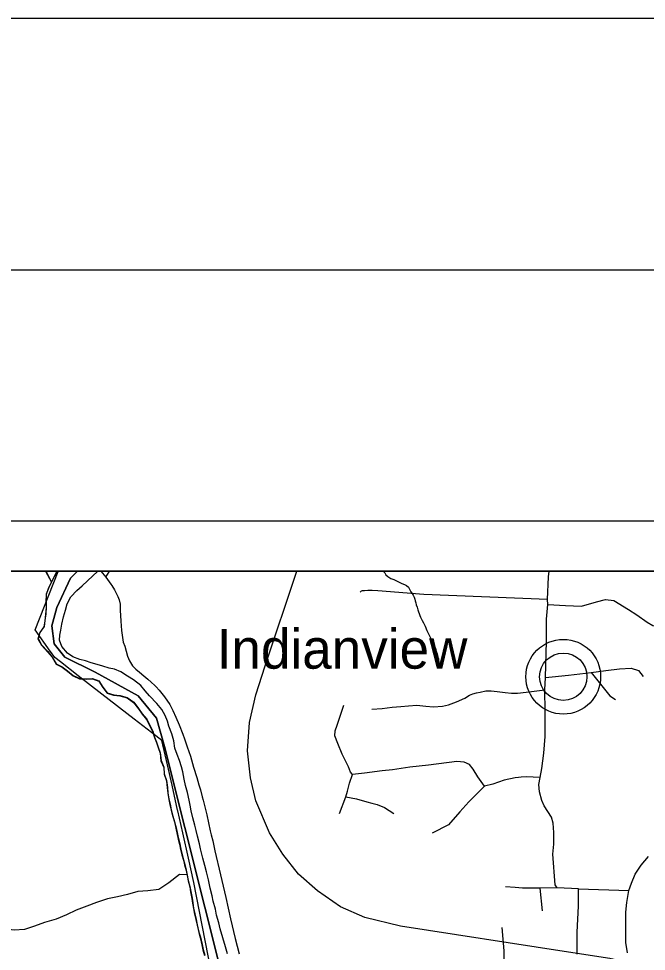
# Model space of a CAD drawing. Extents: x 44.2 to 78.2, y 4.5 to 26.5.
# Drawn here: x 47.924 to 49.173, y 24.644 to 26.501 of the extents above; entities that cross this region are included whole.
import ezdxf

# ---------------------------------------------------------------- set-up
doc = ezdxf.new("R2010")
doc.units = 0
for name, color, linetype in [('GM_X_County_Road', 7, 'Continuous'), ('GM_X_Interstate_Route', 7, 'Continuous'), ('GM_X_Major_River', 7, 'Continuous'), ('GM_X_Minor_River', 7, 'Continuous'), ('GM_X_Rail_Line', 7, 'Continuous'), ('GM_X_State_Route', 7, 'Continuous'), ('GM_X_Township_Road', 7, 'Continuous'), ('GM_X_Unincorporated', 7, 'Continuous'), ('GM_X_Unincorporated_Location', 7, 'Continuous'), ('GM_X_Unincorporated_Text', 7, 'Continuous'), ('SH_Border', 7, 'Continuous'), ('SH_Cut_Line', 7, 'Continuous'), ('SH_Data', 7, 'Continuous')]:
    doc.layers.add(name, color=color, linetype=linetype)

msp = doc.modelspace()

# ---------------------------------------------------------------- linework, layer by layer
at = {"layer": 'GM_X_County_Road'}
for points in [[(49.0354, 24.6387), (49.0354, 24.6825), (49.0377, 24.7339), (49.0377, 24.7688), (48.9957, 24.7705), (48.9915, 24.7764), (48.9868, 24.8374), (48.9889, 24.8572), (48.9889, 24.8804), (48.9878, 24.8992), (48.9844, 24.9111), (48.97, 24.9339), (48.9652, 24.9443), (48.9601, 24.962), (48.9593, 24.976), (48.9615, 24.9904), (48.9652, 25.0085), (48.9689, 25.0387), (48.9715, 25.0716), (48.9715, 25.1225), (48.9708, 25.1646), (48.9722, 25.1893), (48.9741, 25.2616), (48.9746, 25.3056), (48.9772, 25.3347), (48.9765, 25.345), (48.9783, 25.3901), (48.9795, 25.4014)], [(49.1352, 24.6408), (49.132, 24.6614), (49.132, 24.6942), (49.132, 24.7219), (49.134, 24.7414), (49.138, 24.7651), (49.1434, 24.7797), (49.1508, 24.7977), (49.1626, 24.8156), (49.1774, 24.8328)]]:
    msp.add_lwpolyline(points, dxfattribs=at)
at = {"layer": 'GM_X_Interstate_Route'}
msp.add_lwpolyline([(48.3122, 24.5771), (48.2728, 24.7811), (48.2619, 24.8297), (48.2504, 24.8803), (48.2408, 24.9239), (48.2404, 24.9255), (48.2296, 24.9749), (48.2205, 25.0158), (48.2089, 25.0638), (48.2086, 25.0641), (48.1971, 25.0729), (48.1537, 25.1062), (48.0897, 25.156), (48.0421, 25.193), (48.0074, 25.2204), (47.9959, 25.2295), (47.9875, 25.2411), (47.9868, 25.2421), (47.9567, 25.2841), (48.0025, 25.4004), (48.0016, 25.4014), (47.7834, 25.4014)], dxfattribs=at)
at = {"layer": 'GM_X_Major_River'}
for p, q in [((47.9779, 25.4014), (47.9894, 25.3795)), ((47.9779, 25.4014), (47.9894, 25.3793)), ((47.9891, 25.3791), (48.0009, 25.4014)), ((47.9894, 25.3795), (48.0009, 25.4014)), ((48.0009, 25.4014), (47.9894, 25.3796))]:
    msp.add_line(p, q, dxfattribs=at)
for points in [[(47.9774, 25.4014), (47.9775, 25.4013), (47.9891, 25.3791)], [(48.013, 25.3101), (48.0171, 25.3237), (48.0208, 25.3362), (48.0276, 25.3501), (48.0396, 25.3628), (48.0505, 25.3721), (48.0609, 25.3818), (48.0814, 25.4014)], [(48.013, 25.3101), (48.0171, 25.3237), (48.0208, 25.3362), (48.0276, 25.3501), (48.0396, 25.3628), (48.0505, 25.3721), (48.0609, 25.3818), (48.0814, 25.4014)], [(47.9891, 25.3791), (47.9836, 25.3681), (47.9787, 25.3549), (47.9784, 25.3393), (47.9785, 25.3291), (47.9775, 25.3154), (47.9761, 25.3025), (47.9743, 25.2904), (47.966, 25.2787), (47.9624, 25.2663), (47.9693, 25.254), (47.9815, 25.2408), (47.9904, 25.2296), (47.9985, 25.2161), (48.0105, 25.2101), (48.0209, 25.2019), (48.0325, 25.1926), (48.0453, 25.187), (48.0582, 25.1863), (48.0707, 25.1868), (48.0835, 25.1824), (48.0912, 25.1693), (48.1001, 25.1581), (48.1129, 25.154), (48.1254, 25.153), (48.1397, 25.1489), (48.1528, 25.1399), (48.1624, 25.1268), (48.1698, 25.1164), (48.1786, 25.1059), (48.1837, 25.0955), (48.1906, 25.0821), (48.1942, 25.0698), (48.1981, 25.0602), (48.2013, 25.0499), (48.2053, 25.0388), (48.2072, 25.0232), (48.2126, 25.0101), (48.2135, 24.9972), (48.2181, 24.9838), (48.2197, 24.9697), (48.2206, 24.959), (48.2226, 24.9464), (48.225, 24.9365), (48.2275, 24.9254), (48.2306, 24.9124), (48.2338, 24.9017), (48.2369, 24.8891), (48.2397, 24.8768), (48.2417, 24.8673), (48.2442, 24.8577), (48.2462, 24.8467), (48.249, 24.836), (48.2518, 24.8256), (48.2543, 24.8161), (48.2571, 24.805), (48.2591, 24.7951), (48.2612, 24.7844), (48.2643, 24.7725), (48.266, 24.7626), (48.2688, 24.7496), (48.2701, 24.7401), (48.2718, 24.7294), (48.2742, 24.7179), (48.2766, 24.7072), (48.279, 24.6962), (48.2825, 24.6816), (48.2853, 24.6717), (48.2888, 24.6572), (48.2908, 24.6472), (48.294, 24.6361)], [(47.9894, 25.3796), (47.9839, 25.3687), (47.979, 25.3555), (47.9787, 25.3399), (47.9789, 25.3297), (47.9778, 25.316), (47.9764, 25.3031), (47.9746, 25.2909), (47.9664, 25.2793), (47.9627, 25.2669), (47.9696, 25.2545), (47.9819, 25.2414), (47.9907, 25.2301), (47.9988, 25.2167), (48.0108, 25.2107), (48.0213, 25.2025), (48.0328, 25.1932), (48.0456, 25.1876), (48.0585, 25.1869), (48.071, 25.1874), (48.0838, 25.183), (48.0915, 25.1699), (48.1004, 25.1587), (48.1132, 25.1546), (48.1257, 25.1536), (48.1401, 25.1495), (48.1531, 25.1405), (48.1627, 25.1274), (48.1701, 25.1169), (48.179, 25.1065), (48.1841, 25.0961), (48.191, 25.0827), (48.1945, 25.0704), (48.1985, 25.0608), (48.2017, 25.0505), (48.2056, 25.0394), (48.2075, 25.0238), (48.2129, 25.0107), (48.2138, 24.9978), (48.2184, 24.9844), (48.22, 24.9703), (48.2209, 24.9596), (48.2229, 24.947), (48.2254, 24.9371), (48.2278, 24.926), (48.2309, 24.913), (48.2341, 24.9023), (48.2372, 24.8897), (48.24, 24.8774), (48.2421, 24.8679), (48.2445, 24.8583), (48.2466, 24.8473), (48.2494, 24.8365), (48.2522, 24.8262), (48.2546, 24.8167), (48.2574, 24.8056), (48.2595, 24.7956), (48.2615, 24.785), (48.2647, 24.7731), (48.2664, 24.7632), (48.2691, 24.7502), (48.2704, 24.7407), (48.2721, 24.73), (48.2745, 24.7185), (48.2769, 24.7078), (48.2793, 24.6967), (48.2828, 24.6822), (48.2856, 24.6723), (48.2891, 24.6578), (48.2912, 24.6478), (48.2943, 24.6367)], [(48.3396, 24.6394), (48.3354, 24.6532), (48.3301, 24.6708), (48.3248, 24.6891), (48.322, 24.7006), (48.3178, 24.7159), (48.3154, 24.7281), (48.3112, 24.7438), (48.3088, 24.7549), (48.3053, 24.7698), (48.3019, 24.7866), (48.298, 24.8022), (48.2945, 24.8152), (48.2907, 24.8298), (48.2861, 24.8481), (48.2837, 24.8581), (48.2798, 24.8737), (48.2771, 24.8848), (48.2743, 24.8955), (48.2704, 24.9101), (48.2673, 24.9238), (48.2653, 24.9353), (48.2632, 24.9452), (48.2597, 24.9605), (48.2562, 24.9742), (48.2535, 24.9872), (48.2504, 25.0017), (48.2479, 25.0117), (48.244, 25.0239), (48.2397, 25.0362), (48.2347, 25.0488), (48.2327, 25.063), (48.2289, 25.0771), (48.2228, 25.0928), (48.2199, 25.1024), (48.2156, 25.1135), (48.2087, 25.1258), (48.1991, 25.1378), (48.1846, 25.1529), (48.1757, 25.163), (48.1668, 25.1735), (48.1527, 25.1848), (48.1407, 25.1922), (48.1272, 25.2009), (48.1144, 25.2057), (48.1042, 25.2082), (48.0917, 25.2119), (48.0801, 25.2156), (48.068, 25.2185), (48.0571, 25.2225), (48.0457, 25.2254), (48.0318, 25.2306), (48.0209, 25.2377), (48.0102, 25.2512), (48.0056, 25.2639), (48.0062, 25.2734), (48.0079, 25.2836), (48.0097, 25.2953), (48.013, 25.3101)]]:
    msp.add_lwpolyline(points, dxfattribs=at)
at = {"layer": 'GM_X_Minor_River'}
for points in [[(48.6503, 25.4014), (48.6509, 25.4), (48.6524, 25.3977), (48.6549, 25.3938), (48.6587, 25.3907), (48.6646, 25.3868), (48.6706, 25.3843), (48.6759, 25.3819), (48.6796, 25.3799), (48.6849, 25.3771), (48.6898, 25.3755), (48.692, 25.3747), (48.6958, 25.3727), (48.6995, 25.3695)], [(48.6995, 25.3695), (48.7013, 25.3665), (48.7046, 25.3603), (48.7072, 25.3568), (48.709, 25.3534), (48.7108, 25.3495), (48.7122, 25.3457), (48.7132, 25.3419), (48.7143, 25.3384), (48.7153, 25.3342), (48.7167, 25.3293), (48.7185, 25.3243), (48.7199, 25.3204), (48.721, 25.317), (48.7224, 25.3128), (48.7238, 25.3097), (48.7249, 25.3067), (48.7271, 25.3028), (48.7296, 25.2982), (48.7328, 25.2913), (48.7364, 25.2828), (48.7382, 25.279), (48.7411, 25.2736), (48.7422, 25.2713), (48.7451, 25.2659), (48.7466, 25.2628), (48.748, 25.2601), (48.7495, 25.2578), (48.7509, 25.2548), (48.7523, 25.2502), (48.7534, 25.2475), (48.7541, 25.2448), (48.7551, 25.2421), (48.7565, 25.2368), (48.7576, 25.233), (48.7579, 25.2299), (48.7593, 25.2265), (48.7596, 25.2234), (48.761, 25.2181), (48.762, 25.2143)], [(48.2594, 24.7962), (48.244, 24.7968), (48.2226, 24.7808), (48.2028, 24.7675), (48.1811, 24.7648), (48.1613, 24.7633), (48.1403, 24.7572), (48.1209, 24.7526), (48.1007, 24.7488), (48.0789, 24.7416), (48.0599, 24.734), (48.0385, 24.726), (48.0195, 24.7169), (47.9989, 24.7081), (47.9756, 24.7013), (47.9558, 24.694), (47.9356, 24.6876), (47.9154, 24.6864), (47.8941, 24.6887), (47.8731, 24.6868), (47.8525, 24.6811), (47.8316, 24.675), (47.8125, 24.6598), (47.8102, 24.6571)]]:
    msp.add_lwpolyline(points, dxfattribs=at)
at = {"layer": 'GM_X_Rail_Line'}
for points in [[(48.3347, 24.571), (48.2145, 25.0522), (48.1984, 25.1081), (48.1616, 25.1532), (48.076, 25.2002), (48.016, 25.2302), (47.9948, 25.2567), (47.9902, 25.2922), (47.9997, 25.3285), (48.0269, 25.3874), (48.0411, 25.4014), (46.8824, 25.4014)], [(53.1359, 25.4014), (48.0411, 25.4014), (48.0269, 25.3874), (47.9997, 25.3285), (47.9902, 25.2922), (47.9948, 25.2567), (48.016, 25.2302), (48.076, 25.2002), (48.1616, 25.1532), (48.1984, 25.1081), (48.2145, 25.0522), (48.3347, 24.571)], [(49.3949, 24.3999), (49.3043, 24.5149), (49.2677, 24.5582), (49.2261, 24.5879), (49.1595, 24.6164), (49.1003, 24.63), (49.0093, 24.6438), (48.6841, 24.6943), (48.6131, 24.7115), (48.5641, 24.7325), (48.5189, 24.7644), (48.4811, 24.798), (48.4497, 24.8379), (48.423, 24.8802), (48.3957, 24.9436), (48.3854, 24.9898), (48.3795, 25.0434), (48.3833, 25.0995), (48.3958, 25.1552), (48.4146, 25.2129), (48.4773, 25.4014)]]:
    msp.add_lwpolyline(points, dxfattribs=at)
at = {"layer": 'GM_X_State_Route'}
for points in [[(48.0874, 25.4014), (48.0973, 25.3892), (48.1075, 25.3751), (48.1092, 25.3726)], [(48.1092, 25.3726), (48.1147, 25.3643), (48.1212, 25.3509), (48.1238, 25.344), (48.1257, 25.3357), (48.1257, 25.3236), (48.1275, 25.3018), (48.1289, 25.2831), (48.132, 25.2595), (48.1356, 25.2521), (48.1409, 25.2321), (48.1448, 25.2224), (48.1508, 25.2128), (48.1569, 25.2057), (48.1642, 25.1998), (48.1734, 25.1925), (48.181, 25.1861), (48.1879, 25.1803), (48.1951, 25.1734), (48.1974, 25.1705), (48.2037, 25.1643), (48.2145, 25.1509), (48.2249, 25.1357), (48.2309, 25.1239), (48.237, 25.1105), (48.2434, 25.0951), (48.2508, 25.0764), (48.2539, 25.0672), (48.2594, 25.0511), (48.2658, 25.0326), (48.2721, 25.0108), (48.2787, 24.9904), (48.2828, 24.9754), (48.2856, 24.966), (48.2891, 24.9517), (48.291, 24.9451), (48.2937, 24.9342), (48.2983, 24.9157), (48.3051, 24.8843), (48.3072, 24.8763), (48.3104, 24.8641), (48.3144, 24.8439), (48.3254, 24.7967), (48.3364, 24.7514), (48.3458, 24.7091), (48.355, 24.6695), (48.3626, 24.639)]]:
    msp.add_lwpolyline(points, dxfattribs=at)
at = {"layer": 'GM_X_Township_Road'}
for p, q in [((48.9121, 24.771), (48.8928, 24.7725)), ((48.9611, 24.7697), (48.9657, 24.725)), ((49.0377, 24.7688), (49.138, 24.7651))]:
    msp.add_line(p, q, dxfattribs=at)
for points in [[(48.0973, 25.3892), (48.1038, 25.3998), (48.1048, 25.4014)], [(48.9765, 25.345), (48.7302, 25.3546), (48.6384, 25.3618), (48.6274, 25.3625), (48.6191, 25.3628), (48.6122, 25.3623), (48.6077, 25.3621), (48.6054, 25.3614), (48.6034, 25.3592)], [(48.9772, 25.3347), (49.0121, 25.3329), (49.0442, 25.3314), (49.0741, 25.3403), (49.0918, 25.3447), (49.1084, 25.3425), (49.1372, 25.3251), (49.1543, 25.3142), (49.1745, 25.2997), (49.1856, 25.293), (49.1985, 25.2908)], [(48.9722, 25.1893), (49.018, 25.1941), (49.0633, 25.1996), (49.0926, 25.2033), (49.1195, 25.2067), (49.1431, 25.2078), (49.1575, 25.2033), (49.1667, 25.1912)], [(49.0633, 25.1996), (49.1003, 25.1528), (49.1114, 25.1458)], [(48.6265, 25.1262), (48.6471, 25.1277), (48.667, 25.1306), (48.6844, 25.1317), (48.6995, 25.1332), (48.7161, 25.134), (48.7342, 25.1321), (48.7493, 25.131), (48.7671, 25.1325), (48.7796, 25.1351), (48.7955, 25.141), (48.812, 25.1485), (48.8212, 25.1539), (48.8278, 25.1571), (48.8351, 25.1591), (48.8423, 25.16), (48.8538, 25.1631), (48.8645, 25.1627), (48.8763, 25.1616), (48.8918, 25.1594), (48.9047, 25.1579), (48.9169, 25.1583), (48.9342, 25.1602), (48.9708, 25.1646)], [(48.5626, 24.9186), (48.5753, 24.952), (48.5781, 24.9629), (48.5822, 24.9791), (48.5884, 24.9959), (48.584, 25.0011), (48.5801, 25.0116), (48.5676, 25.037), (48.5589, 25.0582), (48.553, 25.0734), (48.5537, 25.0832), (48.5578, 25.0948), (48.5711, 25.1343)], [(48.851, 24.9733), (48.8379, 24.9915), (48.8283, 25.007), (48.8213, 25.0162), (48.8106, 25.021), (48.7958, 25.0218), (48.7394, 25.0147), (48.7021, 25.0106), (48.6678, 25.0058), (48.6473, 25.0032)], [(48.6473, 25.0032), (48.6121, 24.9989), (48.5884, 24.9959)], [(48.924, 24.9908), (48.9186, 24.9903), (48.9119, 24.9896), (48.8901, 24.985), (48.8674, 24.9771), (48.851, 24.9733), (48.8197, 24.9421), (48.8017, 24.9221), (48.7796, 24.8963), (48.7471, 24.8793)], [(48.9615, 24.9904), (48.934, 24.9919), (48.924, 24.9908)], [(48.5753, 24.952), (48.5964, 24.9478), (48.617, 24.9421), (48.6268, 24.9389), (48.6377, 24.9365), (48.6521, 24.9308), (48.6706, 24.9188)], [(48.9957, 24.7705), (48.9611, 24.7697), (48.9265, 24.7699), (48.9121, 24.771)], [(48.8866, 24.5097), (48.8874, 24.5371), (48.8885, 24.571), (48.8898, 24.6454), (48.8859, 24.6918)]]:
    msp.add_lwpolyline(points, dxfattribs=at)
at = {"layer": 'GM_X_Unincorporated'}
for radius in [0.0744, 0.0472]:
    msp.add_circle((49.0077, 25.1909), radius, dxfattribs=at)
at = {"layer": 'GM_X_Unincorporated_Location'}
msp.add_line((49.0077, 25.1909), (49.0077, 25.1909), dxfattribs=at)
at = {"layer": 'SH_Border'}
msp.add_lwpolyline([(45.7359, 26.0014), (77.7359, 26.0014), (77.7359, 5.0014), (45.7359, 5.0014)], close=True, dxfattribs=at)
at = {"layer": 'SH_Cut_Line'}
msp.add_lwpolyline([(44.2359, 4.5014), (78.2359, 4.5014), (78.2359, 26.5014), (44.2359, 26.5014)], close=True, dxfattribs=at)
for points in [[(48.3347, 24.571), (48.2145, 25.0522), (48.1984, 25.1081), (48.1616, 25.1532), (48.076, 25.2002), (48.016, 25.2302), (47.9948, 25.2567), (47.9902, 25.2922), (47.9997, 25.3285), (48.0269, 25.3874), (48.0411, 25.4014), (46.3359, 25.4014)], [(53.1359, 25.4014), (48.0411, 25.4014), (48.0269, 25.3874), (47.9997, 25.3285), (47.9902, 25.2922), (47.9948, 25.2567), (48.016, 25.2302), (48.076, 25.2002), (48.1616, 25.1532), (48.1984, 25.1081), (48.2145, 25.0522), (48.3347, 24.571)]]:
    msp.add_lwpolyline(points, dxfattribs=at)
at = {"layer": 'SH_Data'}
for p, q in [((46.2359, 25.5014), (53.2359, 25.5014)), ((46.3359, 25.4014), (53.1359, 25.4014))]:
    msp.add_line(p, q, dxfattribs=at)

# ---------------------------------------------------------------- texts
at = {"layer": 'GM_X_Unincorporated_Text'}
msp.add_text('Indianview', height=0.07898, rotation=0, dxfattribs=at).set_placement((48.318, 25.207))

doc.saveas('drawing.dxf')
